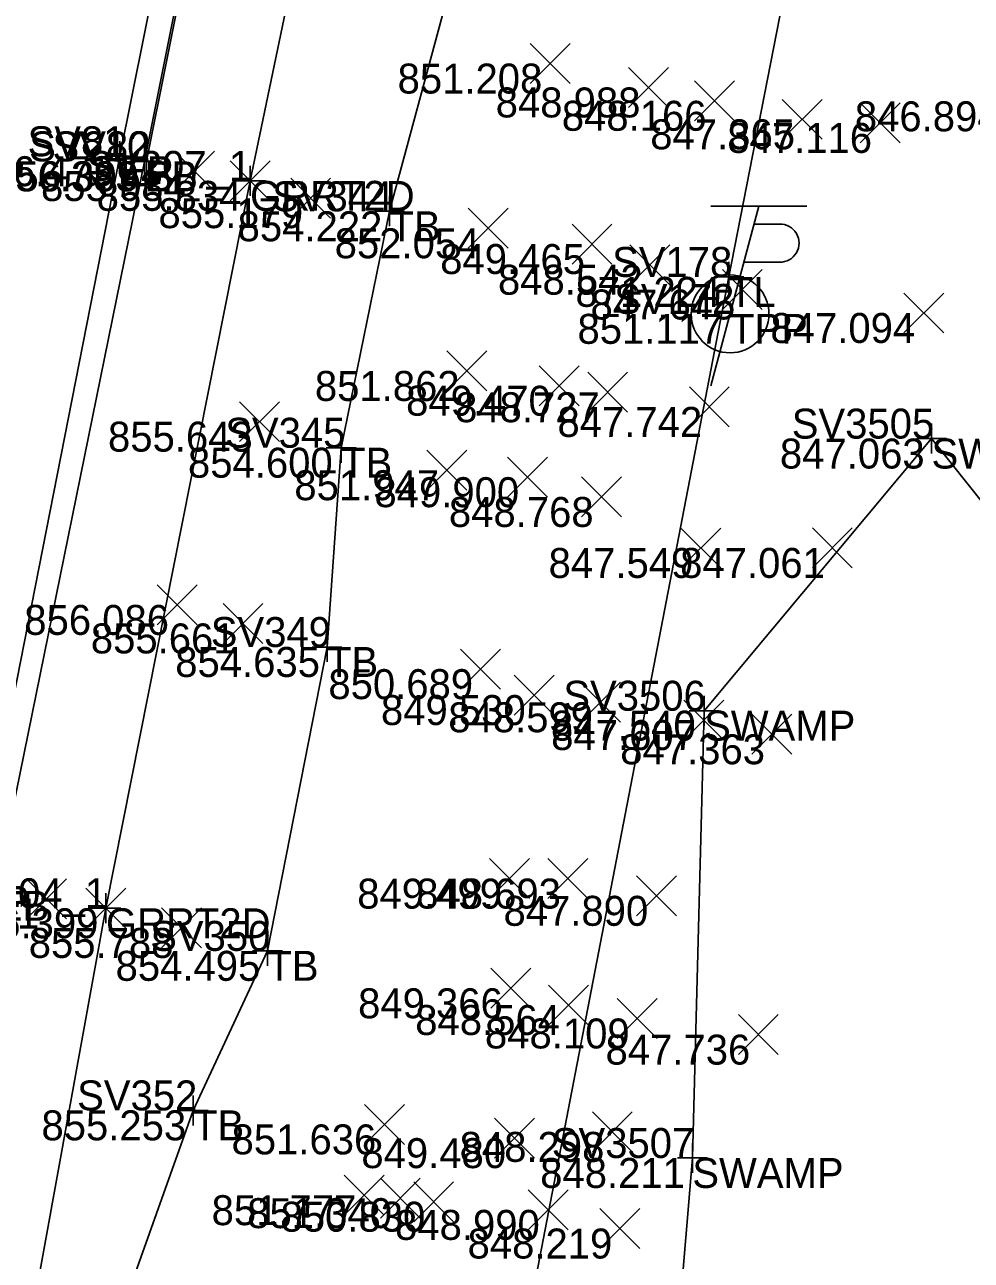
# Model space of a CAD drawing. Extents: x 2228183 to 2230895, y 679226 to 682223.
# Drawn here: x 2228313.99 to 2228345.61, y 680526.83 to 680568.09 of the extents above; entities that cross this region are included whole.
import ezdxf

# ---------------------------------------------------------------- set-up
doc = ezdxf.new("R2010")
doc.units = 0
for name, color, linetype in [('HY_X_Water_Edge', 7, 'Continuous'), ('PV_X_EOP', 7, 'Continuous'), ('PV_X_Shoulder_Aggregate', 7, 'Continuous'), ('RD_X_GR_Rt', 7, 'Continuous'), ('SC_Scratch1', 7, 'Continuous'), ('SV_P_Control_Cells_Set', 7, 'Continuous'), ('SV_X_Break_Lines', 7, 'Continuous'), ('SV_X_Random_Point', 7, 'Continuous'), ('SV_X_Shot_Marker', 7, 'Continuous'), ('SV_X_Text_Comment', 7, 'Continuous'), ('SV_X_Top_of_Bank', 7, 'Continuous'), ('UT_X_Misc_Cells', 7, 'Continuous'), ('UT_X_Telecom', 7, 'Continuous')]:
    doc.layers.add(name, color=color, linetype=linetype)

msp = doc.modelspace()

# ---------------------------------------------------------------- linework, layer by layer
at = {"layer": 'HY_X_Water_Edge'}
msp.add_lwpolyline([(2228388.587, 680538.705), (2228381.654, 680540.428), (2228373.267, 680534.114), (2228362.534, 680538.041), (2228352.058, 680544.515), (2228344.28, 680554.272), (2228336.684, 680545.185), (2228336.291, 680530.248), (2228335.4, 680519.473), (2228335.533, 680511.573), (2228332.556, 680502.567), (2228338.972, 680492.245), (2228338.927, 680481.209), (2228345.953, 680472.044), (2228352.301, 680471.046)], dxfattribs=at)
at = {"layer": 'PV_X_EOP'}
msp.add_lwpolyline([(2228272.958, 680193.788), (2228272.514, 680218.749), (2228272.761, 680243.66), (2228273.456, 680268.53), (2228274.726, 680293.686), (2228276.435, 680318.586), (2228278.817, 680343.424), (2228281.861, 680368.095), (2228285.158, 680392.512), (2228289.018, 680417.009), (2228293.5, 680441.465), (2228298.055, 680466.05), (2228302.846, 680490.329), (2228307.636, 680514.848), (2228312.366, 680539.332), (2228317.173, 680563.701), (2228322.066, 680588.07), (2228326.883, 680612.686), (2228331.837, 680637.002), (2228336.903, 680661.667), (2228341.796, 680685.984)], dxfattribs=at)
at = {"layer": 'PV_X_Shoulder_Aggregate'}
msp.add_lwpolyline([(2228273.386, 680193.772), (2228272.957, 680218.691), (2228273.264, 680243.644), (2228274.133, 680268.478), (2228275.472, 680293.621), (2228277.239, 680318.511), (2228279.649, 680343.317), (2228282.622, 680367.988), (2228285.854, 680392.371), (2228289.575, 680416.853), (2228293.89, 680441.38), (2228298.61, 680465.949), (2228303.2, 680490.238), (2228308.065, 680514.741), (2228313.026, 680539.169), (2228317.996, 680563.53), (2228322.869, 680587.896), (2228327.71, 680612.549), (2228332.443, 680636.855), (2228337.368, 680661.526), (2228342.398, 680685.817)], dxfattribs=at)
at = {"layer": 'RD_X_GR_Rt'}
msp.add_lwpolyline([(2228290.359, 680391.22), (2228294.274, 680415.932), (2228298.414, 680440.801), (2228302.718, 680465.177), (2228307.188, 680489.321), (2228312.206, 680513.859), (2228316.706, 680538.587), (2228321.519, 680562.878), (2228326.574, 680587.113), (2228331.32, 680611.864), (2228336.079, 680636.156), (2228341.093, 680660.882), (2228346.244, 680685.06), (2228350.849, 680709.572), (2228355.751, 680733.95), (2228357.804, 680743.718), (2228360.585, 680755.706), (2228364.08, 680768.892), (2228368.125, 680781.145)], dxfattribs=at)
at = {"layer": 'SV_X_Break_Lines'}
msp.add_lwpolyline([(2228318.056, 680563.531), (2228321.526, 680580.804), (2228322.934, 680587.943), (2228323.641, 680591.395), (2228326.787, 680607.417), (2228327.798, 680612.502), (2228328.969, 680618.417), (2228330.908, 680628.604), (2228332.526, 680636.825), (2228334.967, 680649.168), (2228337.431, 680661.516)], dxfattribs=at)
at = {"layer": 'SV_X_Random_Point'}
for p, q in [((2228330.88, 680566.128), (2228332.214, 680567.463)), ((2228330.88, 680567.463), (2228332.214, 680566.128)), ((2228334.156, 680565.33), (2228335.49, 680566.665)), ((2228334.156, 680566.665), (2228335.49, 680565.33)), ((2228336.368, 680564.885), (2228337.702, 680566.22)), ((2228336.368, 680566.22), (2228337.702, 680564.885)), ((2228339.289, 680564.266), (2228340.623, 680565.601)), ((2228339.289, 680565.601), (2228340.623, 680564.266)), ((2228341.896, 680564.145), (2228343.23, 680565.48)), ((2228341.896, 680565.48), (2228343.23, 680564.145)), ((2228318.994, 680562.538), (2228320.328, 680563.873)), ((2228318.994, 680563.873), (2228320.328, 680562.538)), ((2228320.852, 680562.211), (2228322.186, 680563.546)), ((2228320.852, 680563.546), (2228322.186, 680562.211)), ((2228322.876, 680561.633), (2228324.21, 680562.968)), ((2228322.876, 680562.968), (2228324.21, 680561.633)), ((2228328.801, 680560.627), (2228330.135, 680561.962)), ((2228328.801, 680561.962), (2228330.135, 680560.627)), ((2228332.273, 680560.102), (2228333.607, 680561.437)), ((2228332.273, 680561.437), (2228333.607, 680560.102)), ((2228334.205, 680559.411), (2228335.539, 680560.746)), ((2228334.205, 680560.746), (2228335.539, 680559.411)), ((2228337.294, 680558.583), (2228338.628, 680559.918)), ((2228337.294, 680559.918), (2228338.628, 680558.583)), ((2228343.355, 680557.799), (2228344.689, 680559.134)), ((2228343.355, 680559.134), (2228344.689, 680557.799)), ((2228328.09, 680555.863), (2228329.424, 680557.198)), ((2228328.09, 680557.198), (2228329.424, 680555.863)), ((2228331.177, 680555.37), (2228332.511, 680556.705)), ((2228331.177, 680556.705), (2228332.511, 680555.37)), ((2228332.796, 680555.152), (2228334.13, 680556.487)), ((2228332.796, 680556.487), (2228334.13, 680555.152)), ((2228336.192, 680554.662), (2228337.526, 680555.997)), ((2228336.192, 680555.997), (2228337.526, 680554.662)), ((2228321.172, 680554.17), (2228322.506, 680555.505)), ((2228321.172, 680555.505), (2228322.506, 680554.17)), ((2228327.427, 680552.548), (2228328.761, 680553.883)), ((2228327.427, 680553.883), (2228328.761, 680552.548)), ((2228330.12, 680552.315), (2228331.454, 680553.65)), ((2228330.12, 680553.65), (2228331.454, 680552.315)), ((2228332.593, 680551.655), (2228333.927, 680552.99)), ((2228332.593, 680552.99), (2228333.927, 680551.655)), ((2228335.907, 680549.951), (2228337.241, 680551.286)), ((2228335.907, 680551.286), (2228337.241, 680549.951)), ((2228340.299, 680549.953), (2228341.633, 680551.288)), ((2228340.299, 680551.288), (2228341.633, 680549.953)), ((2228318.415, 680548.05), (2228319.749, 680549.385)), ((2228318.415, 680549.385), (2228319.749, 680548.05)), ((2228320.616, 680547.431), (2228321.95, 680548.766)), ((2228320.616, 680548.766), (2228321.95, 680547.431)), ((2228328.552, 680545.905), (2228329.886, 680547.24)), ((2228328.552, 680547.24), (2228329.886, 680545.905)), ((2228330.339, 680545.04), (2228331.673, 680546.375)), ((2228330.339, 680546.375), (2228331.673, 680545.04)), ((2228332.557, 680544.798), (2228333.891, 680546.133)), ((2228332.557, 680546.133), (2228333.891, 680544.798)), ((2228336.006, 680544.205), (2228337.34, 680545.54)), ((2228336.006, 680545.54), (2228337.34, 680544.205)), ((2228338.281, 680543.73), (2228339.615, 680545.065)), ((2228338.281, 680545.065), (2228339.615, 680543.73)), ((2228329.516, 680538.909), (2228330.85, 680540.244)), ((2228329.516, 680540.244), (2228330.85, 680538.909)), ((2228331.465, 680538.911), (2228332.799, 680540.246)), ((2228331.465, 680540.246), (2228332.799, 680538.911)), ((2228314.057, 680538.24), (2228315.391, 680539.575)), ((2228314.057, 680539.575), (2228315.391, 680538.24)), ((2228334.431, 680538.335), (2228335.765, 680539.67)), ((2228334.431, 680539.67), (2228335.765, 680538.335)), ((2228316.039, 680537.92), (2228317.373, 680539.255)), ((2228316.039, 680539.255), (2228317.373, 680537.92)), ((2228318.56, 680537.263), (2228319.894, 680538.598)), ((2228318.56, 680538.598), (2228319.894, 680537.263)), ((2228329.564, 680535.247), (2228330.898, 680536.582)), ((2228329.564, 680536.582), (2228330.898, 680535.247)), ((2228331.491, 680534.689), (2228332.825, 680536.024)), ((2228331.491, 680536.024), (2228332.825, 680534.689)), ((2228333.782, 680534.239), (2228335.116, 680535.574)), ((2228333.782, 680535.574), (2228335.116, 680534.239)), ((2228337.829, 680533.7), (2228339.163, 680535.035)), ((2228337.829, 680535.035), (2228339.163, 680533.7)), ((2228325.338, 680530.702), (2228326.672, 680532.037)), ((2228325.338, 680532.037), (2228326.672, 680530.702)), ((2228329.684, 680530.243), (2228331.018, 680531.578)), ((2228329.684, 680531.578), (2228331.018, 680530.243)), ((2228332.952, 680530.452), (2228334.286, 680531.787)), ((2228332.952, 680531.787), (2228334.286, 680530.452)), ((2228324.665, 680528.338), (2228325.999, 680529.673)), ((2228324.665, 680529.673), (2228325.999, 680528.338)), ((2228325.872, 680528.239), (2228327.206, 680529.574)), ((2228325.872, 680529.574), (2228327.206, 680528.239)), ((2228326.985, 680528.121), (2228328.319, 680529.456)), ((2228326.985, 680529.456), (2228328.319, 680528.121)), ((2228330.809, 680527.847), (2228332.143, 680529.182)), ((2228330.809, 680529.182), (2228332.143, 680527.847)), ((2228333.201, 680527.224), (2228334.535, 680528.559)), ((2228333.201, 680528.559), (2228334.535, 680527.224))]:
    msp.add_line(p, q, dxfattribs=at)
at = {"layer": 'SV_X_Shot_Marker'}
for p, q in [((2228317.173, 680564.201), (2228317.173, 680563.201)), ((2228317.996, 680564.03), (2228317.996, 680563.03)), ((2228318.056, 680564.031), (2228318.056, 680563.031)), ((2228316.673, 680563.701), (2228317.673, 680563.701)), ((2228317.173, 680563.701), (2228317.173, 680563.701)), ((2228317.496, 680563.53), (2228318.496, 680563.53)), ((2228317.556, 680563.531), (2228318.556, 680563.531)), ((2228317.996, 680563.53), (2228317.996, 680563.53)), ((2228318.056, 680563.531), (2228318.056, 680563.531)), ((2228321.519, 680563.378), (2228321.519, 680562.378)), ((2228321.019, 680562.878), (2228322.019, 680562.878)), ((2228321.519, 680562.878), (2228321.519, 680562.878)), ((2228326.177, 680562.362), (2228326.177, 680561.362)), ((2228325.677, 680561.862), (2228326.677, 680561.862)), ((2228326.177, 680561.862), (2228326.177, 680561.862)), ((2228337.511, 680560.172), (2228337.511, 680559.172)), ((2228337.011, 680559.672), (2228338.011, 680559.672)), ((2228337.511, 680559.672), (2228337.511, 680559.672)), ((2228344.28, 680554.772), (2228344.28, 680553.772)), ((2228324.56, 680554.467), (2228324.56, 680553.467)), ((2228343.78, 680554.272), (2228344.78, 680554.272)), ((2228344.28, 680554.272), (2228344.28, 680554.272)), ((2228324.06, 680553.967), (2228325.06, 680553.967)), ((2228324.56, 680553.967), (2228324.56, 680553.967)), ((2228324.09, 680547.812), (2228324.09, 680546.812)), ((2228323.59, 680547.312), (2228324.59, 680547.312)), ((2228324.09, 680547.312), (2228324.09, 680547.312)), ((2228336.684, 680545.685), (2228336.684, 680544.685)), ((2228336.184, 680545.185), (2228337.184, 680545.185)), ((2228336.684, 680545.185), (2228336.684, 680545.185)), ((2228316.706, 680539.087), (2228316.706, 680538.087)), ((2228316.206, 680538.587), (2228317.206, 680538.587)), ((2228316.706, 680538.587), (2228316.706, 680538.587)), ((2228322.098, 680537.665), (2228322.098, 680536.665)), ((2228321.598, 680537.165), (2228322.598, 680537.165)), ((2228322.098, 680537.165), (2228322.098, 680537.165)), ((2228319.616, 680532.338), (2228319.616, 680531.338)), ((2228319.116, 680531.838), (2228320.116, 680531.838)), ((2228319.616, 680531.838), (2228319.616, 680531.838)), ((2228336.291, 680530.748), (2228336.291, 680529.748)), ((2228335.791, 680530.248), (2228336.791, 680530.248)), ((2228336.291, 680530.248), (2228336.291, 680530.248))]:
    msp.add_line(p, q, dxfattribs=at)
at = {"layer": 'SV_X_Top_of_Bank'}
msp.add_lwpolyline([(2228351.296, 680683.864), (2228348.585, 680671.422), (2228345.681, 680659.56), (2228343.564, 680646.922), (2228341.433, 680634.625), (2228339.657, 680626.067), (2228337.837, 680616.265), (2228336.717, 680610.616), (2228334.631, 680604.814), (2228334.097, 680599.023), (2228332.268, 680590.812), (2228331.694, 680589.223), (2228331.741, 680585.744), (2228330.895, 680582.337), (2228329.944, 680577.766), (2228328.503, 680570.479), (2228326.177, 680561.862), (2228324.56, 680553.967), (2228324.09, 680547.312), (2228322.098, 680537.165), (2228319.616, 680531.838), (2228317.404, 680525.616)], dxfattribs=at)
at = {"layer": 'UT_X_Misc_Cells'}
for p, q in [((2228338.514, 680562.037), (2228336.908, 680556.037)), ((2228340.114, 680562.037), (2228336.914, 680562.037)), ((2228338.354, 680561.437), (2228339.204, 680561.437)), ((2228338.013, 680560.162), (2228339.204, 680560.162))]:
    msp.add_line(p, q, dxfattribs=at)
msp.add_circle((2228337.551, 680558.437), 1.3, dxfattribs=at)
msp.add_arc((2228339.217, 680560.8), 0.638, 268.8767, 91.1233, dxfattribs=at)
at = {"layer": 'UT_X_Telecom'}
msp.add_lwpolyline([(2228306.801, 680400.49), (2228337.511, 680559.672), (2228349.317, 680620.055), (2228359.383, 680671.523), (2228365.58, 680702.692), (2228381.421, 680781.425)], dxfattribs=at)

# ---------------------------------------------------------------- texts
at = {"layer": 'SC_Scratch1'}
for s, p in [('851.208', (2228326.447, 680565.795)), ('848.988', (2228329.723, 680564.997)), ('848.166', (2228331.931, 680564.552)), ('846.894', (2228341.718, 680564.534)), ('847.365', (2228334.886, 680563.933)), ('847.116', (2228337.459, 680563.812)), ('856.473', (2228312.109, 680562.701)), ('856.383', (2228312.932, 680562.53)), ('856.309', (2228312.972, 680562.531)), ('855.984', (2228314.539, 680562.205)), ('855.834', (2228316.397, 680561.878)), ('855.834', (2228316.397, 680561.878)), ('855.179', (2228318.459, 680561.3)), ('854.222', (2228321.104, 680560.862)), ('852.054', (2228324.346, 680560.294)), ('849.465', (2228327.87, 680559.769)), ('848.542', (2228329.799, 680559.078)), ('871.224', (2228332.389, 680558.672)), ('847.645', (2228332.891, 680558.25)), ('851.117', (2228332.455, 680557.437)), ('847.094', (2228338.9, 680557.466)), ('851.862', (2228323.684, 680555.53)), ('849.470', (2228326.73, 680555.037)), ('848.727', (2228328.367, 680554.819)), ('847.742', (2228331.786, 680554.329)), ('855.643', (2228316.775, 680553.837)), ('847.063', (2228339.216, 680553.272)), ('854.600', (2228319.446, 680552.967)), ('851.947', (2228322.998, 680552.215)), ('849.900', (2228325.673, 680551.982)), ('848.768', (2228328.16, 680551.322)), ('847.549', (2228331.49, 680549.618)), ('847.061', (2228335.884, 680549.62)), ('856.086', (2228313.978, 680547.717)), ('855.661', (2228316.201, 680547.098)), ('854.635', (2228319.02, 680546.312)), ('850.689', (2228324.135, 680545.572)), ('849.530', (2228325.892, 680544.707)), ('848.599', (2228328.14, 680544.465)), ('847.540', (2228331.57, 680544.185)), ('847.607', (2228331.577, 680543.872)), ('847.363', (2228333.884, 680543.397)), ('849.499', (2228325.099, 680538.576)), ('848.693', (2228327.068, 680538.578)), ('847.890', (2228329.984, 680538.002)), ('856.711', (2228309.642, 680537.907)), ('856.399', (2228311.622, 680537.587)), ('856.399', (2228311.622, 680537.587)), ('855.788', (2228314.127, 680536.93)), ('854.495', (2228317.028, 680536.165)), ('849.366', (2228325.127, 680534.914)), ('848.564', (2228327.036, 680534.356)), ('848.109', (2228329.365, 680533.906)), ('847.736', (2228333.392, 680533.367)), ('855.253', (2228314.552, 680530.838)), ('851.636', (2228320.901, 680530.369)), ('849.480', (2228325.237, 680529.91)), ('848.298', (2228328.519, 680530.119)), ('848.211', (2228331.209, 680529.248)), ('851.777', (2228320.236, 680528.005)), ('851.340', (2228321.425, 680527.906)), ('850.830', (2228322.538, 680527.788)), ('848.990', (2228326.362, 680527.514)), ('848.219', (2228328.784, 680526.891))]:
    msp.add_text(s, height=1, dxfattribs=at).set_placement(p)
at = {"layer": 'SV_P_Control_Cells_Set'}
for s, p in [('SV81', (2228314.089, 680563.701)), ('SV210', (2228314.142, 680563.531)), ('SV82', (2228314.921, 680563.53)), ('SV207_1', (2228316.054, 680562.878)), ('SV344', (2228322.255, 680561.862)), ('SV178', (2228333.611, 680559.672)), ('SV172', (2228333.678, 680558.437)), ('SV3505', (2228339.611, 680554.272)), ('SV345', (2228320.69, 680553.967)), ('SV349', (2228320.206, 680547.312)), ('SV3506', (2228331.982, 680545.185)), ('SV204_1', (2228311.241, 680538.587)), ('SV350', (2228318.184, 680537.165)), ('SV352', (2228315.743, 680531.838)), ('SV3507', (2228331.597, 680530.248))]:
    msp.add_text(s, height=1, dxfattribs=at).set_placement(p)
at = {"layer": 'SV_X_Text_Comment'}
for s, p in [('EP', (2228317.173, 680562.701)), ('EB', (2228317.996, 680562.53)), ('B', (2228318.056, 680562.531)), ('GRRT2D', (2228321.519, 680561.878)), ('TB', (2228326.177, 680560.862)), ('TL', (2228337.511, 680558.672)), ('TPP', (2228337.551, 680557.437)), ('SWAMP', (2228344.28, 680553.272)), ('TB', (2228324.56, 680552.967)), ('TB', (2228324.09, 680546.312)), ('SWAMP', (2228336.684, 680544.185)), ('EP', (2228312.366, 680538.332)), ('EB', (2228313.026, 680538.169)), ('GRRT2D', (2228316.706, 680537.587)), ('TB', (2228322.098, 680536.165)), ('TB', (2228319.616, 680530.838)), ('SWAMP', (2228336.291, 680529.248))]:
    msp.add_text(s, height=1, dxfattribs=at).set_placement(p)

doc.saveas('drawing.dxf')
